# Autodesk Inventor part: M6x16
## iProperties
Created: 2006-05
Part Number: M6x16
Material: Kupfer
Document SubType Name: Modeling
Designer: Hendriks
SBm.TeileNr: N00203417
SBm.TeileRev: 00
SBm.Rohteil: -
SBm.Werkstoff: -
SBm.Gewicht: 0.0005
SBm.BenennD: Senkschraube
SBm.BenennE: countersunk screw
SBm.AenIndex1: 0.0
SBm.AenDatum1: 2006-03-31
SBm.AenName1: -
SBm.AenIndex2: 0.0
SBm.AenDatum2: 2006-03-31
SBm.AenName2: -
SBm.InvVersion: 10.0
SBm.EntstAus: -
SBm.ZchgFormat: -
SBm.Norm: DIN963
SBm.Hersteller: -
SBm.Groesse: M6x16
SBm.TeileKennung: -
Author: Hendriks
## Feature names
1. Extrusion1
2. Extrusion2
3. Extrusion3
4. Extrusion4
5. Fase1 [Chamfer]
6. Rundung1 [Fillet]
7. Fase2 [Chamfer]
8. Fase3 [Chamfer]
